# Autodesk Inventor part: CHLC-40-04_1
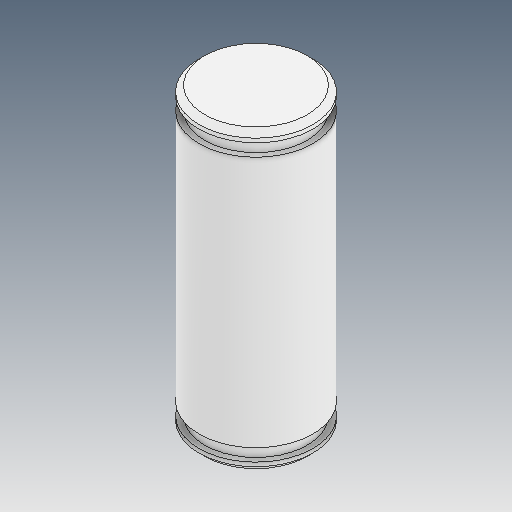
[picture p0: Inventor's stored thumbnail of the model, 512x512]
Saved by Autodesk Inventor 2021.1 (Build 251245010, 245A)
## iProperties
Created: 2021-05
Part Number: CHLC-40-04_1
Material: Ogólny
Document SubType Name: Modeling
Designer: user
Density: 1 g/cm^3
Appearance: Domyślna
Author: user
Revision Number: ÈÎºÎ
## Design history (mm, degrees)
feature "ÊäÈë1"
node "Bryła1"
